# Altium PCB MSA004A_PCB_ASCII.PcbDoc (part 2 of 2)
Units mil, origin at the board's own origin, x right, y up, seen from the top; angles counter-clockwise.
Board outline 2300 x 2720 mil, 2 copper layers (Top Layer, Bottom Layer), stack 62 mil thick; 117 components, 85 nets, 350 pads, 179 vias.
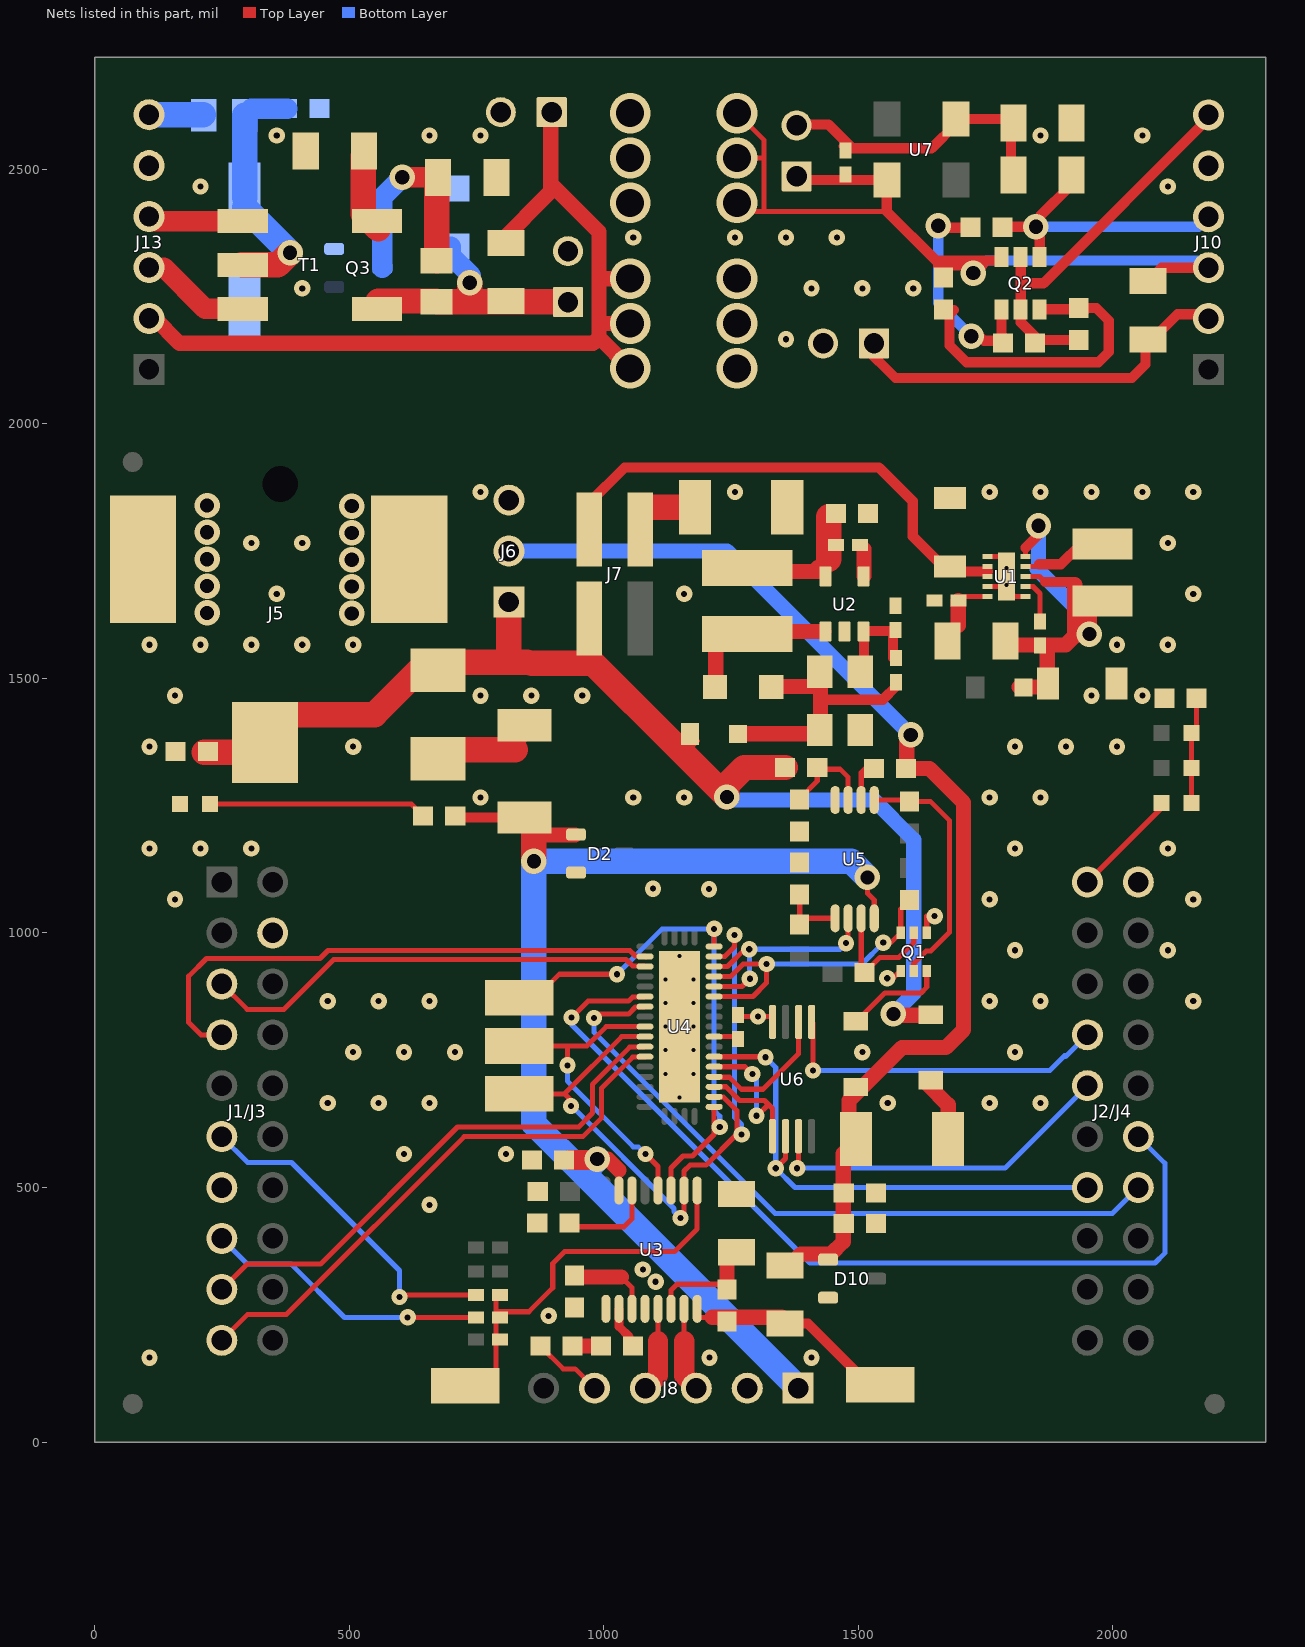
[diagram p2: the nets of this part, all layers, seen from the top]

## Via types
v1: diameter 32, hole 12, Top Layer to Bottom Layer, tented both sides, 125 vias
v2: diameter 50, hole 28, Top Layer to Bottom Layer, 28 vias
v3: diameter 19.68, hole 7.87, Top Layer to Bottom Layer, tented both sides, 14 vias
v4: diameter 80, hole 55, Top Layer to Bottom Layer, 12 vias

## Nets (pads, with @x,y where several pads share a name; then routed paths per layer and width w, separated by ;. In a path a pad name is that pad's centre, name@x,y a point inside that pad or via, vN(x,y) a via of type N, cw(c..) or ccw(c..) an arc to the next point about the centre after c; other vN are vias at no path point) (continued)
GND: C1.2 C2.2 C3.2 C4.2 C5.2 C7.2 C8.2 C9.2 C11.2 C12.2 C14.2 D2.2 D6.2 D10.2 J1/J3.22 J2/J4.20 J5.2 J5.3 J6.3 J8.2 Q1.1 Q1.4 R4.2 R9.2 R10.2 R17.1 R18.2 R23.1 R27.1 U1.1 U1.4 U1.6 U1.11 U2.2 U3.1 U3.4 U4.43 U5.4 U6.4 | length 356.5
  Top Layer w10: U3.4@1081.2,261.86 U3.4@1083.49,264.14 ; R17.1@1248.09,487.09 R17.1@1261,487.09 ; R18.2@1267,835.62 v1@1302.62,835.62 ; v1(1303,836) 1331.61,836 U6.4@1331.61,825.2 ; v1(1557,911) 1568,911 1582.6,925.6 Q1.4@1583.41,925.6 ; Q1.1@1634.59,1000.4 1634.59,1033 v1(1650,1033) ; U1.4@1753.6,1680.32 1782.81,1680.32 U1.11@1782.81,1691.81 ; U1.1@1753.6,1739.37 1791,1739.37 U1.11@1791,1700 v3(1791,1683.62) 1791,1676.69 1807.06,1660.63 U1.6@1828.4,1660.63
  other v1: 108,166 1208,166 1408,166 892,248 1102,315 1077,339 658,466 608,566 808,566 458,666 558,666 658,666 1558,666 1758,666 1858,666 508,766 608,766 708,766 1508,766 1808,766 458,866 558,866 658,866 1758,866 1858,866 2158,866 1808,966 2108,966 158,1066 1758,1066 2158,1066 1207,1086 1097,1087 108,1166 208,1166 308,1166 1808,1166 2108,1166 758,1266 1058,1266 1158,1266 1758,1266 1858,1266 108,1366 508,1366 1808,1366 1908,1366 2008,1366 158,1466 758,1466 858,1466 958,1466 1958,1466 2058,1466 108,1566 208,1566 308,1566 408,1566 508,1566 2008,1566 2108,1566 358,1666 1158,1666 2158,1666 308,1766 408,1766 2108,1766 758,1866 1258,1866 1758,1866 1858,1866 1958,1866 2058,1866 2158,1866
  other v2: 221,1628.5 505,1627.5 505,1680.25 221,1681.25 505,1733 221,1734 505,1785.75 221,1786.75 505,1838.5 221,1839.5
  other v3: 1149,677.22 1121.44,723.48 1176.56,723.48 1121.44,769.74 1176.56,769.74 1121.44,816 1176.56,816 1121.44,862.26 1176.56,862.26 1121.44,908.52 1176.56,908.52 1149,954.78 1791,1716.38
GND_DD: J10.5 J11.2 R35.1
  other v1: 1358,2166 1408,2266 1508,2266 1608,2266 1258,2366 1358,2366 1458,2366 2108,2466 1858,2566 2058,2566
  other v4: 1262,2109 1262,2197 1262,2285
GND_XD: C16.1 C17.2 J12.2 J13.5 J14.2 Q3.2 R38.1 R39.1 R40.1
  other v1: 408,2266 1058,2366 208,2466 358,2566 658,2566 758,2566
  other v4: 1052,2434 1052,2522 1052,2610
GNDP: C13.2 R17.2 U3.6 | length 526.2
  Top Layer w10: U3.6@1132.39,261.86 1132.39,298.39 1144,310 ; C13.2@1242,299.5 C13.2@1242,310 ; R17.2@1242,353.91 R17.2@1261,372.91 ; 1144,310 C13.2@1242,310 ; 1144,310 C13.2@1242,310 ; 1144,310 C13.2@1242,310 ; 1144,310 C13.2@1242,310
  Top Layer w30: C13.2@1242,310 R17.2@1242,353.91
INN: C11.1 U3.3 | length 159.9
  Top Layer w10: 1034.5,324.5 1055.61,303.39 U3.3@1055.61,261.86
  Top Layer w30: C11.1@946,324.5 1034.5,324.5
INP: C10.1 U3.2 | length 81.1
  Top Layer w17: U3.2@1030.02,261.86 1030.02,226.98 1049.99,207.01 C10.1@1049.99,189
INP_DD: J10.2 J11.1 R32.2 | length 777
  Top Layer w20: J11.1@1512,2151 1573,2090 2037,2090 2064,2117 2064,2152 2127,2215 2179.57,2215 J10.2@2187.95,2206.63
INP_XD: J13.2 J14.1 R36.2 | length 1747.7
  Top Layer w30: J13.2@116.5,2208.5 167,2158 979,2158 991,2170 ; R36.2@795.08,2354.93 896,2455.85 896,2610 J14.1@898,2612 ; 896,2472 991,2377 991,2197 ; 993,2285 v4(1052,2285) ; v4(1052,2109) 991,2170 ; v4(1052,2197) 991,2197 ; 991,2170 991,2197
IO: C12.1 C14.1 D10.1 D12.2 J6.2 R15.1 R20.1 R22.2 | length 2320.1
  Top Layer w10: R15.1@1340.25,348.07 1347.32,341 R15.1@1359,341 ; 1413.5,369.65 D10.1@1424.76,358.4
  Top Layer w30: R15.1@1359,341 1387.65,369.65 1446.65,369.65 1470.5,393.5 1470.5,566.5 1493,589 R20.1@1501,589 ; R20.1@1481.95,639.73 1481.95,670.95 1586,775 1672,775 1706.75,809.75 1706.75,1256.25 1640,1323 R22.2@1593.5,1323 ; R22.2@1594.99,1331 1594.99,1380.99 v2(1603,1389)
  Bottom Layer w10: v2(1603,1389) 1603,1376 v2@1608,1371
  Bottom Layer w30: J6.2@810,1761 821,1750 1242,1750 v2@1608,1384
IO_460: C13.1 R15.2 TP4.1 U3.8 | length 437.3
  Top Layer w10: U3.8@1183.57,261.86 1183.57,248.43 1187,245 1217,245 ; R15.2@1356,232.91 R15.2@1366.91,222 ; TP4.1@1521,113 TP4.1@1543,113
  Top Layer w20: R15.2@1356,232.91 1401.09,232.91 TP4.1@1521,113
  Top Layer w30: 1213,245 1217,245 R15.2@1349.91,245
IOREG: C9.1 U3.14 | length 560.1
  Top Layer w10: U3.14@1055.61,494.14 1055.61,438.61 1040,423 ; C9.1@943.5,423 1040,423 ; C9.1@943.5,423 1040,423 ; C9.1@943.5,423 1040,423 ; C9.1@943.5,423 1040,423 ; C9.1@943.5,423 1040,423
MAIN: C1.1 D1.2 D4.1 D11.2 J5.1 J6.1 J7.1 R24.2 | length 2328.8
  Top Layer w10: D4.1@1177.76,1389 1166,1389 1143,1366 1173,1366 D4.1@1184,1377
  Top Layer w30: v2@1571.53,838.47 D11.2@1627,838.47
  Top Layer w50: C1.1@215.5,1355 J5.1@316.06,1355 ; J5.1@344.03,1399.03 374,1429 550,1429 653,1532 849.58,1532 ; 814,1541 J6.1@814,1649 ; 858.57,1529.43 979.57,1529.43 1143,1366 v2(1242,1267) 1242,1291 1276,1325 R24.2@1356.5,1325
  Bottom Layer w30: v2@1234,1270 1242.86,1261.14 1530.86,1261.14 1609,1183 1609,881 v2(1569,841)
MAIN_LOCAL: C2.1 J7.2 U1.2 U1.3 | length 970.8
  Top Layer w10: U1.3@1753.6,1700 1754.6,1709.69
  Top Layer w20: J7.2@972,1792.4 972,1845 1041,1914 1541,1914 1548,1907 1607,1848 1607,1779 1667.9,1718.1 C2.1@1678,1718.1 ; C2.1@1702.24,1709.69 1754.6,1709.69
MEM_CS: J2/J4.37 U6.1 | length 662.2
  Top Layer w10: v1(1411,730) U6.1@1411,822.59
  Bottom Layer w10: v1(1411,730) 1876,730 1905,759 1907,757 J2/J4.37@1950,800
MEM_HOLD: J2/J4.36 U6.7 | length 714.1
  Top Layer w10: v1@1382.8,540.8 U6.7@1382.8,600.8 ; J2/J4.36@1950,683 J2/J4.36@1950,700
  Bottom Layer w10: v1(1380,538) 1788,538 J2/J4.36@1950,700
MEM_MISO: U4.25 U6.2 | length 267.4
  Top Layer w10: U4.25@1216.91,717.57 1217.82,716.67 1246.7,716.67 1270.37,693 1313,693 1382.8,762.8 U6.2@1382.8,825.2
MEM_MOSI: U4.24 U4.26 U6.5 | length 386.2
  Top Layer w10: U4.24@1216.91,697.89 1240.21,697.89 1267,671.1 1315.9,671.1 1323.76,663.24 ; U4.26@1216.91,737.26 1277.74,737.26 v1(1292,723) ; v1(1300,641) 1301.52,641 1323.76,663.24 ; U6.5@1331.61,600.8 1331.61,655.39 1323.76,663.24
  Bottom Layer w10: v1(1292,723) 1300,715 v1(1300,641)
MISO_LP: J1/J3.9 U4.11 | length 1061.6
  Top Layer w10: J1/J3.9@250,300 299.6,349.6 443.66,349.6 713.06,619 951,619 978.25,646.25 978.25,702.68 1051.3,775.72 1080.18,775.72 U4.11@1081.09,776.63
MOSI_LP: J1/J3.10 U4.12 | length 1095.9
  Top Layer w10: J1/J3.10@250,200 301,251 377,251 726,600 959.07,600 996.13,637.06 996.13,695.28 1056.89,756.04 1080.18,756.04 U4.12@1081.09,756.94
NetC3_1: C3.1 D3.2 L1.2 R2.1 R3.2 U1.8 U1.10 | length 881.6
  Top Layer w10: R3.2@1783.09,1576 R3.2@1793.71,1565.38 ; U1.8@1828.4,1700 1856,1700 1867,1689 ; U1.10@1828.4,1739.37 1828.4,1756.4 ; C3.1@1866.07,1483 C3.1@1871,1487.93
  Top Layer w20: 1828.4,1756.4 1854,1782 v2(1854,1800) ; 1867,1689 1925,1689
  Top Layer w30: R3.2@1793.71,1565.38 1871,1565.38 ; D3.2@1816.24,1483 C3.1@1866.07,1483 ; C3.1@1871,1487.93 1871,1565.38 ; 1925,1684 1925,1582.96 1907.42,1565.38 1871,1565.38 ; v2(1954,1587) 1954,1622 1950,1626 L1.2@1976,1652
  Bottom Layer w30: v2(1854,1800) 1854,1718 1851,1715 1950.62,1615.38 v2@1950.62,1599.56
NetC4_1: C4.1 C6.1 D4.2 D5.1 R6.2 | length 536.3
  Top Layer w10: C6.1@1425,1514 C6.1@1426,1513 ; R6.2@1575,1485 R6.2@1575,1493.38
  Top Layer w20: 1424,1458 1548,1458 R6.2@1575,1485
  Top Layer w30: D4.2@1273.24,1391 1417,1391 1426,1400 C6.1@1426,1513 ; D5.1@1330.12,1484 C6.1@1425,1484
NetC5_1: C5.1 L2.1 R5.2 R7.1 U2.5 | length 239.6
  Top Layer w10: R7.1@1450.38,1756 R7.1@1456.5,1762.13
  Top Layer w30: L2.1@1290.96,1710 1427.73,1710 1419.87,1717.87
  Top Layer w50: 1442,1734 C5.1@1442,1817
NetC6_2: C6.2 R6.1 R9.1 U2.3 | length 190.4
  Top Layer w10: C6.2@1505,1514 C6.2@1511.4,1520.4
  Top Layer w20: C6.2@1511.4,1520.4 1511.4,1592.87 1568,1592.87 R6.1@1568,1540.62
NetC10_2: C10.2 R41.2 | length 56
  Top Layer w30: R41.2@938.5,189 C10.2@994.5,189
NetC15_1: C15.1 J12.1 R36.1 R38.2 T1.4 | length 485.6
  Top Layer w10: C15.1@670.87,2241.13 C15.1@672,2240 C15.1@672.09,2239.91
  Top Layer w50: T1.4@556.86,2241.13 C15.1@670.87,2241.13 ; C15.1@672.09,2239.91 776,2239.91 J12.1@915.09,2239.91 ; 737,2239.91 v2(737,2277)
  Bottom Layer w40: R38.2@700,2347.91 700,2330.33 739.5,2290.83 v2@739.5,2274.5
NetC15_2: C15.2 Q3.3 R40.2 | length 406.1
  Top Layer w10: 646.86,2484 R40.2@671.91,2484
  Top Layer w40: v2(604.23,2484.17) 646.69,2484.17 646.86,2484
  Top Layer w50: C15.2@672,2320 R40.2@672,2464
  Bottom Layer w40: Q3.3@565.24,2306 565.24,2445.18 v2(604.23,2484.17)
NetC16_2: C16.2 C17.1 R37.2 T1.2 | length 482.2
  Top Layer w50: T1.2@289.14,2312 360,2312 v2(384,2336)
  Bottom Layer w10: C17.1@295,2425 C17.1@295,2444.3
  Bottom Layer w40: R37.2@308,2619 C16.2@378.5,2619
  Bottom Layer w50: C17.1@295,2425 v2(384,2336) ; C17.1@295,2444.3 R37.2@295,2606
NetD1_1: D1.1 R1.1 | length 189.4
  Top Layer w10: D1.1@675,1341.99 D1.1@693.01,1360 ; 826.45,1360 R1.1@848,1381.55
  Top Layer w50: D1.1@693.01,1360 826.45,1360
NetD5_2: D5.2 L2.2 U2.1 | length 337.3
  Top Layer w10: L2.2@1219.88,1569.88 1238.04,1588.04 1283,1588.04 L2.2@1287.83,1592.87
  Top Layer w30: D5.2@1219.88,1484 L2.2@1219.88,1569.88 ; L2.2@1258,1592 U2.1@1432,1592
NetD6_1: D6.1 R8.2 | length 428.5
  Top Layer w10: D6.1@226.53,1253 622.5,1253 R8.2@645.5,1230
NetD7_2: D7.2 D8.2 D9.2 R10.1 | length 210.1
  Top Layer w10: D7.2@2154.53,1255 D8.2@2154.53,1324 2154.53,1392.94 2164.5,1402.91 R10.1@2164.5,1461
NetD11_1: D11.1 R20.2 | length 133.8
  Top Layer w30: D11.1@1636,712 1636,703 1676.55,662.45 R20.2@1676.55,595
NetD12_1: D12.1 Q1.6 | length 207.1
  Top Layer w10: D12.1@1496,817.47 1504,825.47 1504,834 1552.13,882.13 1623.13,882.13 1634.59,893.59 Q1.6@1634.59,925.6
NetJ9_2: J9.2 R33.1 R34.2 R35.2 U7.3 | length 610.8
  Top Layer w10: J9.2@1373,2573 J9.2@1373,2588 ; R33.1@1466.62,2545 R33.1@1475,2536.62
  Top Layer w20: J9.2@1373,2588 1441,2588 1488,2541 1644,2541 1691.91,2588.91 U7.3@1691.91,2598.66 1795.25,2598.66 1798.91,2595 1799.91,2594 R34.2@1799.91,2488
NetL1_1: L1.1 U1.9 | length 126.6
  Top Layer w10: U1.9@1828.4,1719.69 1850.69,1719.69 1855,1724
  Top Layer w20: 1855,1724 1898,1724 L1.1@1937.04,1763.04
NetQ1_2: Q1.2 R25.1 U5.7 | length 240.5
  Top Layer w10: R25.1@1505.8,928.7 U5.7@1505.8,1028.86 ; R25.1@1512.5,922 1542.62,952.13 1580.13,952.13 1609,981 Q1.2@1609,1000.4
NetQ1_5: Q1.5 R21.1 U5.1 | length 493.8
  Top Layer w10: U5.1@1531.39,1261.14 1598.35,1261.14 R21.1@1601,1258.5 1641.5,1258.5 1678.87,1221.13 1678.87,1000.87 1642.61,964.61 1633.61,964.61 1609,940 Q1.5@1609,925.6
NetQ2_1: Q2.1 R29.1 R31.1 | length 441.7
  Top Layer w20: v2(1657,2389) 1661,2385 R31.1@1712.5,2385 ; v2(1722,2172) 1738,2172 1747,2163 1792.5,2163 1781.6,2173.91 Q2.1@1781.6,2224.82
  Bottom Layer w20: v2(1657,2389) 1657,2237 v2(1722,2172)
NetQ2_3: Q2.3 R28.1 R30.1 | length 642.9
  Top Layer w20: 1688,2223.5 1679.13,2214.63 1679.13,2154.24 1712.49,2120.87 1971.87,2120.87 1992,2141 1992,2203 1967.5,2227.5 R28.1@1933,2227.5 ; Q2.3@1856.4,2224.82 1945.68,2224.82 1946.45,2224.05 R28.1@1933,2224.05
NetR2_2: R2.2 U1.7 | length 88.5
  Top Layer w10: U1.7@1828.4,1680.32 1843.68,1680.32 1844.13,1679.87 1844.13,1679.53 1857,1666.65 R2.2@1857,1612.62
NetR3_1: R3.1 R4.1 U1.5 | length 342.4
  Top Layer w10: R4.1@1696.62,1653 1704.25,1660.63 U1.5@1753.6,1660.63 ; R3.1@1668.91,1576 R3.1@1696.62,1603.71 ; R3.1@1668.91,1576 R3.1@1670.41,1577.5 ; R3.1@1668.91,1576 R3.1@1696.62,1603.71 ; R3.1@1668.91,1576 R3.1@1696.62,1603.71 ; R3.1@1668.91,1576 R3.1@1696.62,1603.71 ; R3.1@1670.41,1577.5 R3.1@1696.62,1603.71 ; R3.1@1670.41,1577.5 R3.1@1696.62,1603.71
  Top Layer w30: R3.1@1696.62,1603.71 R4.1@1696.62,1653
NetR7_2: R7.2 U2.4 | length 67
  Top Layer w10: R7.2@1498.62,1757 1508.62,1757 R7.2@1511.4,1754.22
  Top Layer w30: U2.4@1511.4,1701.13 R7.2@1511.4,1754.22
NetR18_1: R18.1 U4.29 | length 42.1
  Top Layer w10: U4.29@1216.91,796.32 R18.1@1259.06,796.32
NetR22_1: R22.1 U5.2 | length 284.7
  Top Layer w10: U5.2@1505.8,1261.14 1505.8,1315.3 ; R22.1@1523,1332.5 1505.8,1315.3 ; 1505.8,1315.3 R22.1@1522,1331.5 ; 1505.8,1315.3 R22.1@1522,1331.5 ; 1505.8,1315.3 R22.1@1522,1331.5 ; 1505.8,1315.3 R22.1@1522,1331.5 ; 1505.8,1315.3 R22.1@1522,1331.5 ; 1505.8,1315.3 R22.1@1522,1331.5 ; 1505.8,1315.3 R22.1@1522,1331.5 ; 1505.8,1315.3 R22.1@1522,1331.5 ; 1505.8,1315.3 R22.1@1522,1331.5
NetR23_2: R23.2 R24.1 U5.3 | length 244.2
  Top Layer w10: R23.2@1385,1251.5 1385,1263.78 1419.5,1298.28 1419.5,1321.5 1464.5,1321.5 ; R24.1@1416.5,1321.5 1464.5,1321.5 ; U5.3@1480.2,1261.14 1480.2,1305.8 1464.5,1321.5
NetR26_2: R26.2 R27.2 U5.5 | length 136.2
  Top Layer w10: R26.2@1385,1006 R27.2@1385,1072.57 ; R26.2@1385,1028.86 U5.5@1454.61,1028.86
NetR39_2: R39.2 T1.6 | length 155
  Top Layer w50: R39.2@528,2525.91 528,2411.72 T1.6@556.86,2382.87
OUTA: J8.4 U3.5 | length 148.1
  Top Layer w10: 1106.8,198 U3.5@1106.8,243.86
  Top Layer w40: J8.4@1082,106 1106.8,130.8 1106.8,198
OUTA_DD: J9.1 J10.3 Q2.6 R30.2 R32.1 R33.2 U7.1 | length 1795.7
  Top Layer w10: v4(1262,2434) 1279.09,2416.91 1556.09,2416.91 ; v4(1262,2522) 1315.12,2522 ; v4(1262,2610) 1315.12,2556.88 1315.12,2522 ; 1315.12,2419.21 1315.12,2522 ; R30.2@1660.5,2286.5 R30.2@1668.25,2294.25
  Top Layer w20: J9.1@1373,2488 1382.41,2478.59 U7.1@1556.09,2478.59 1556.09,2416.91 1652,2321 1775.42,2321 Q2.6@1781.6,2327.18 ; 1657,2311 v2@1744,2311 ; v2@1721.5,2311 1726,2306.5 v2(1726,2296) ; R32.1@2069,2280.09 2095.54,2306.63 J10.3@2187.95,2306.63
  Bottom Layer w20: v2@1734,2303 1752,2321 2173.57,2321 J10.3@2187.95,2306.63
OUTA_XD: J13.3 T1.3 | length 200.5
  Top Layer w10: J13.3@107.05,2307 J13.3@136,2307
  Top Layer w40: J13.3@136,2307 217,2226 T1.3@274.01,2226
OUTB: J8.3 U3.7 | length 147.8
  Top Layer w10: 1157.98,198 U3.7@1157.98,243.86
  Top Layer w40: 1157.98,198 1157.98,130.02 J8.3@1182,106
OUTB_DD: J10.4 Q2.4 R31.2 R34.1 | length 650.2
  Top Layer w20: R31.2@1775.5,2385 1777.5,2387 v2(1849,2387) 1856.4,2379.6 Q2.4@1856.4,2327.18 1856.4,2407.32 R34.1@1917.09,2468
  Bottom Layer w20: v2(1849,2387) 2168.32,2387 J10.4@2187.95,2406.63
OUTB_XD: J13.4 T1.1 | length 179.8
  Top Layer w10: J13.4@107.05,2407 J13.4@116.05,2398
  Top Layer w40: J13.4@116.05,2398 T1.1@283.14,2398
OWI_RXD: Q1.3 R19.2 U4.33 U4.35 | length 624.9
  Top Layer w10: U4.33@1216.91,875.06 1293.06,875.06 1320,902 v1(1320,939.13) 1274.13,939.13 1249.43,914.43 U4.35@1216.91,914.43 ; v1(1549,981) 1564.01,981 Q1.3@1583.41,1000.4 1583.41,1046.91 R19.2@1601,1064.5
  Bottom Layer w10: v1(1320,939.13) 1507.13,939.13 v1(1549,981)
OWI_TXD: U4.34 U4.36 U5.6 | length 467.6
  Top Layer w10: U4.34@1216.91,894.74 1271.74,894.74 v1(1287,910) v1@1287,904.48 ; U4.36@1216.91,934.11 1243.39,934.11 1277.28,968 v1(1286,968) ; v1(1476,980) 1480.2,984.2 U5.6@1480.2,1028.86
  Bottom Layer w10: v1@1286,911 v1(1286,968) 1464,968 v1(1476,980)
RTRN: J8.5 R41.1 | length 158.4
  Top Layer w10: R41.1@875.5,189 920.5,144 944,144 J8.5@982,106 J8.5@964.5,106
RXD_460: TP1.1 U3.11 U4.22 U4.38 | length 1077.6
  Top Layer w10: TP1.1@834,873 867,873 913,919 v1(1026,919) ; U3.11@1132.39,494.14 1132.39,538.39 1155.83,561.83 1174.67,561.83 1216.91,604.08 U4.22@1216.91,658.52 ; U4.38@1216.91,973.48 v1(1216.91,1008.09)
  Bottom Layer w10: v1(1026,919) 1115.09,1008.09 v1(1216.91,1008.09) 1216.91,651.09 1228,640 v1(1228,619)
RXD_LP: J1/J3.3 U4.3 | length 898
  Top Layer w10: J1/J3.3@250,900 300,850 372,850 469.87,947.87 1044.03,947.87 1056.89,935.02 1080.18,935.02 U4.3@1081.09,934.11
SCLK_460: TP3.1 U3.12 U4.9 | length 625.2
  Top Layer w10: TP3.1@834,778 967,778 1005,816 U4.9@1081.09,816 ; v1(929,740) 929,777 ; v1(1082,566) 1106.8,541.2 U3.12@1106.8,494.14
  Bottom Layer w10: v1(929,740) 929,709 1058,580 1068,580 v1(1082,566)
SCLK_LP: J2/J4.34 U4.27 U6.6 | length 1025.9
  Top Layer w10: U4.27@1216.91,756.94 v1@1318,756.94 ; v1(1338,538) 1357.2,557.2 U6.6@1357.2,600.8
  Bottom Layer w10: v1(1318,756) 1338,736 v1(1338,538) 1376,500 J2/J4.34@1950,500
TCI_CLK: J1/J3.7
TCI_RX: J2/J4.14 U4.7 | length 1375
  Top Layer w10: v1(981,833) 989,841 1049,841 1062.48,854.46 1080.18,854.46 U4.7@1081.09,855.37
  Bottom Layer w10: v1(981,833) 981,805 1337,449 1999,449 J2/J4.14@2050,500
TCI_TX: J2/J4.15 U4.6 | length 1778.4
  Top Layer w10: v1@946.92,843.92 969,866 1048.74,866 1056.89,874.15 1080.18,874.15 U4.6@1081.09,875.06
  Bottom Layer w10: v1(937,834) 937,820 1405,352 2083,352 2102.13,371.13 2102.13,547.87 J2/J4.15@2050,600
TEST: R13.1 R14.1 R16.1 TP5.1 U3.9 | length 785.6
  Top Layer w10: TP5.1@728,111 756,111 788.5,143.5 R14.1@788.5,256 ; R16.1@788.5,289 R14.1@788.5,256 ; U3.9@1183.57,494.14 1183.57,418.57 1139,374 923,374 900,351 900,303 853,256 R14.1@788.5,256
TEST_A: J1/J3.6 R16.2 | length 662
  Top Layer w10: v1(599,285) 600,285 604,289 R16.2@749.38,289
  Bottom Layer w10: J1/J3.6@250,600 301,549 387,549 599,337 v1(599,285)
TEST_D: J1/J3.8 R14.2 | length 563.6
  Top Layer w10: v1(615,245) R14.2@749.38,245
  Bottom Layer w10: J1/J3.8@250,400 300.4,349.6 386.4,349.6 491,245 v1(615,245)
TXD_460: TP2.1 U3.10 U4.10 U4.23 U4.37 | length 1444.2
  Top Layer w10: TP2.1@834,684 923,684 ; 912,684 923,684 ; v1(936,660) 936,671 923,684 ; U4.10@1081.09,796.32 1035.32,796.32 923,684 ; v1(1151,440) 1157.98,446.98 U3.10@1157.98,494.14 1157.98,532.44 1169.49,543.96 1200.96,543.96 1262,605 1262,650.82 1235.52,677.3 1235.15,677.3 1234.24,678.2 U4.23@1216.91,678.2 ; U4.37@1216.91,953.8 1237.8,953.8 1256.13,972.13 1256.13,972.96 1257,973.83 v1(1257,996)
  Bottom Layer w10: v1(936,660) 937.07,660 1138,459.07 1138,453 v1(1151,440) ; v1(1257,996) 1257,638 1271,624 v1(1271,604)
TXD_LP: J1/J3.4 U4.2 | length 1107.2
  Top Layer w10: J1/J3.4@262,788 J1/J3.4@250,800 209.14,800 185,824.14 185,915 220,950 443,950 458.7,965.7 462.42,965.7 462.47,965.75 1051.43,965.75 1062.48,954.7 1081.39,954.7 U4.2@1083.09,953
V_DIAG_LED: D7.1 J2/J4.40 | length 215.3
  Top Layer w10: J2/J4.40@1950,1100 2095.47,1245.47 D7.1@2095.47,1255
VIN_USB_ONLY: J7.4 R5.1 | length 141.7
  Top Layer w10: J7.4@1072,1792.4 1072,1820 J7.4@1088,1836
  Top Layer w50: J7.4@1088,1836 R5.1@1179.45,1836
VPWR: C8.1 D2.1 J8.1 R1.2 R8.1 U3.15 U5.8 | length 2424.5
  Top Layer w10: R1.2@863,1208.47 879.06,1192.4 ; v2@985.5,554 v2(987.5,556) ; U3.15@1030.02,494.14 1030.02,533.98 ; v2(1518,1109) 1518,1078 1531.39,1064.61 U5.8@1531.39,1028.86
  Top Layer w20: R8.1@708.5,1227 R1.2@800,1227
  Top Layer w30: 879.06,1192.4 D2.1@943.76,1192.4 ; v2(987.5,556) 1008,556 1030.02,533.98
  Top Layer w40: C8.1@933.5,554 v2@985.5,554
  Top Layer w50: v2(863,1141) R1.2@863,1208.47
  Bottom Layer w50: v2(987.5,556) 959.75,528.25 ; J8.1@1382,106 959.75,528.25 ; v2@1510,1117 1486,1141 v2(863,1141) 863,625 959.75,528.25
VPWR_DD: J10.6 Q2.2 Q2.5 R28.2 R29.2 | length 767.2
  Top Layer w20: Q2.5@1819,2327.18 1819,2276 ; R28.2@1933,2164.51 1857,2164.51 1855.5,2163 1819,2199.5 Q2.2@1819,2224.82 1819,2276 ; J10.6@2187.95,2606.63 2187.95,2599.98 1863.97,2276 1819,2276
VPWR_XD: J13.6 R37.1 | length 106.9
  Bottom Layer w50: J13.6@107.05,2607 R37.1@214,2607
pads on no net: D2.3 D10.3 FID1.1 FID2.1 FID3.1 FID4.1 FID5.1 FID6.1 J1/J3.23 J1/J3.24 J1/J3.25 J1/J3.26 J1/J3.27 J1/J3.28 J1/J3.29 J1/J3.30 J2/J4.11 J2/J4.12 J2/J4.13 J2/J4.16 J2/J4.19 J2/J4.31 J2/J4.32 J2/J4.33 J2/J4.35 J5.0 SH-J1.0 U4.1 U4.4 U4.8 U4.14 U4.15 U4.16 U4.17 U4.18 U4.19 U4.20 U4.21 U4.28 U4.30 U4.31 U4.32 U4.40 U4.41 U4.42 U6.3 U7.2 U7.4

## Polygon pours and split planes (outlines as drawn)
GND_DD on Top Layer "Top-GNDD" (solid, pour order 19): 1159,2720 1159,2012 2300,2012 2300,2720
GND_XD on Top Layer "Top-GNDX" (solid, pour order 17): 0,2009 1141,2009 1141,2720 0,2720
GND on Top Layer "Top-GND" (solid, pour order 15): 0,0 1224,0 1224,152 1226.64,158.36 1236.64,168.36 cw(c1243,162) 1243,171 1304.99,171 1311.36,168.36 1340.36,139.36 1343,133 1343,0 2300,0 2300,1991 0,1991
GND_DD on Bottom Layer "Btm-GNDD" (solid, pour order 18): 1159,2800 1159,2012 2300,2012 2300,2800
GND_XD on Bottom Layer "Btm-GNDX" (solid, pour order 16): 0,2009 1141,2009 1141,2800 0,2800
GND on Bottom Layer "Btm-GND" (solid, pour order 14): 0,0 1161.57,0 1161.57,26.45 750,450.6 750,500 842.76,500 842.76,494.76 1224,113.52 1224,9 1341.8,9 1341.8,101 1360,119.2 1360,3 1359.49,0 2300,0 2300,1991 0,1991

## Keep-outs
Keep-Out Layer:
  text ".Layer_Name" at 577,-858.49 h60

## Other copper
Top Layer:
  rectangle net NetR39_2: 497,2354 605.32,2422
  rectangle net NetC15_1: 497,2201 605.32,2269
  rectangle net OUTB_XD: 239,2355 347.32,2423
  rectangle net NetC16_2: 239,2278 347.32,2346
  rectangle net OUTA_XD: 239,2201 347.32,2269
  rectangle net NetC5_1: 1326,1713 1445,1838
  rectangle net INP_XD: 979,2109 1052,2300
  rectangle net OUTA_DD: 1261,2419.21 1315.12,2640
  text ".Layer_Name" at 577,-858.49 h60
Bottom Layer:
  text ".Layer_Name" at 577,-858.49 h60

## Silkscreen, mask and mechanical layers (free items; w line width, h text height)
Top Overlay:
  lines w10: 947,1527 947,1320 1099,1320 1099,1527 ; 1002,2088 1002,2313 ; 1002,2409 1002,2634 ; 1022,1321 1022,1528 ; 1313,2088 1313,2313 ; 1313,2409 1313,2634
  text "-" at 1093,2619 h72.83
  text "+" at 1188.87,2600.23 h72.83
  text "VPWR" at 183.13,2591 h30 r45
  text "-" at 1093,2530.5 h72.83
  text "+" at 1188.87,2511.73 h72.83
  text "+" at 900,2508 h72.83
  text "GND" at 183.38,2491.61 h30 r45
  text "-" at 1093,2442 h72.83
  text "+" at 1188,2435 h72.83
  text "OUTB" at 183.38,2391.96 h30 r45
  text "+" at 1356,2389 h72.83
  text "OUTA" at 183.38,2292.31 h30 r45
  text "-" at 1205,2242 h72.83
  text "+" at 1093,2235 h72.83
  text "+" at 1502,2219 h72.83
  text "RTRN" at 183.13,2192.41 h30 r45
  text "-" at 1205,2153.5 h72.83
  text "+" at 1093,2146.5 h72.83
  text "+" at 900,2139 h72.83
  text "DCPL" at 183.38,2093 h30 r45
  text "-" at 1205,2065 h72.83
  text "+" at 1093,2058 h72.83
  text "Transformer Driven" at 310,2047 h72.83
  text "Direct Driven" at 1526,2047 h72.83
  text "GND" at 753,1817 h60 r90
  text "IO" at 753,1729 h60 r90
  text "PWR" at 754,1578 h60 r90
  text "DS-LED" at 1868.03,1375.97 h60
  text "X-EXT" at 1004,1341 h60 r90
  text "LP-USB" at 1082,1340 h60 r90
  text "FD-LED" at 1871,1305 h60
  text "Alt Pwr" at 932,1272 h60
  text "VD-LED" at 1864,1237 h60
  text "VPWR-LED" at 264,1234 h60
  text "Modes" at 947,1230 h60
  text "1" at 239,1167 h55
  text "21" at 323,1167 h55
  text "40" at 1925,1167 h55
  text "20" at 2024,1167 h55
  text "J1" at 133,1164 h72.83
  text "J3" at 405,1164 h72.83
  text "J4" at 1825,1164 h72.83
  text "J2" at 2104,1164 h72.83
  text "5V" at 480.5,1078 h72.83
  text "3V3" at 23.75,1076.5 h72.83
  text "GND" at 2146.25,1075.75 h72.83
  text "GND" at 449.25,977 h72.83
  text "VDLED" at 1790,968 h60 r45
  text "COM_P" at 2100,899 h60 r315
  text "DECA*" at 97,891 h60 r45
  text "FDLED" at 1796,868 h60 r45
  text "COM_S" at 2100,798 h60 r315
  text "UARX" at 110.66,796 h60 r45
  text "DSLED" at 1793,768 h60 r45
  text "MCS" at 1836,706 h60 r45
  text "UATX" at 114.86,697 h60 r45
  text "TCITX" at 2090.86,600 h60 r315
  text "MHLD" at 1814,580 h60 r45
  text "DECD*" at 96.76,579 h60 r45
  text "TCIRX" at 2090.86,500 h60 r315
  text "TSTA*" at 108,490 h60 r45
  text "BOOSTXL-PGA460" at 682,442 h85 r90
  text "MSA004A" at 741,441 h70 r90
  text "SCLK" at 1806,389 h60 r45
  text "TCICK" at 96,374 h60 r45
  text "TSTD*" at 103.2,291 h60 r45
  text "MISO" at 123,201 h60 r45
  text "31" at 1928,98 h55
  text "11" at 2027,98 h55
  text "10" at 227,97 h55
  text "30" at 325,97 h55
  text "MOSI" at 122,96 h60 r45
  text "GND" at 1339,74.62 h30 r90
  text "DCPL" at 941,71 h30 r90
  text "RTRN" at 1041,67 h30 r90
  text "OUTA" at 1141,66 h30 r90
  text "OUTB" at 1240,66.38 h30 r90
  text "VPWR" at 1442,64 h30 r90
  text ".Layer_Name" at 577,-858.49 h60
Bottom Overlay:
  drawing of 3493 lines, arcs and shapes, not listed
  text "MSA004A" at 1230,2660 h40
  text "-" at 1093,2619 h72.83
  text "VPWR" at 2126.13,2606 h30 r45
  text "+" at 1188.87,2600.23 h72.83
  text "-" at 1093,2530.5 h72.83
  text "+" at 1188.87,2511.73 h72.83
  text "+" at 900,2508 h72.83
  text "GND" at 2125.87,2506.61 h30 r45
  text "-" at 1093,2442 h72.83
  text "+" at 1188,2435 h72.83
  text "OUTB" at 2125.87,2406.96 h30 r45
  text "+" at 1356,2389 h72.83
  text "OUTA" at 2125.87,2307.31 h30 r45
  text "-" at 1205,2242 h72.83
  text "+" at 1093,2235 h72.83
  text "+" at 1502,2219 h72.83
  text "RTRN" at 2126.13,2207.41 h30 r45
  text "-" at 1205,2153.5 h72.83
  text "+" at 1093,2146.5 h72.83
  text "+" at 900,2139 h72.83
  text "DCPL" at 2125.89,2108 h30 r45
  text "-" at 1205,2065 h72.83
  text "+" at 1093,2058 h72.83
  text "BOOSTXL-PGA460 Daughtercard" at 1432,2034 h40
  text "1" at 297,1160 h55
  text "21" at 397.5,1160 h55
  text "40" at 1999,1160 h55
  text "20" at 2097.5,1160 h55
  text "J4" at 1902.5,1158 h72.83
  text "J1" at 202.5,1154 h72.83
  text "J3" at 479,1154 h72.83
  text "J2" at 2179,1153.5 h72.83
  text "GND" at 2287,1077.5 h72.83
  text "5V" at 553,1077 h72.83
  text "3V3" at 133.25,1076 h72.83
  text "GP40" at 1902,1046 h72.83
  text "GND" at 588,977.5 h72.83
  text "AIN2*" at 197.5,952 h72.83
  text "GP39" at 1902.5,945 h72.83
  text "GP38" at 1902.5,851 h72.83
  text "GP18" at 2284,847 h72.83
  text "UARX" at 207.01,843 h72.83
  text "UATX" at 207.01,753 h72.83
  text "GP17" at 2284,752 h72.83
  text "GP37" at 1902.5,745 h72.83
  text "GP36" at 1902.5,652 h72.83
  text "GP5*" at 197.5,643 h72.83
  text "PGA460-Q1 BoosterPack" at 1717,572.32 h72.83
  text "AIN6*" at 197.5,554 h72.83
  text "MOSI" at 2279,553 h72.83
  text "BOOSTXL-PGA460" at 1717,460.22 h72.83
  text "SCLK" at 1902.5,452 h72.83
  text "MISO" at 2280,447 h72.83
  text "CLK" at 197.5,444 h72.83
  text "Rev A" at 1717,392.36 h60
  text "GP8*" at 197.5,353 h72.83
  text "SOMI" at 197.5,246 h72.83
  text "SIMO" at 197.5,153 h72.83
  text "31" at 1999,92 h55
  text "11" at 2097.5,92 h55
  text "10" at 300,89 h55
  text "30" at 400,89 h55
  text ".Layer_Name" at 577,-858.49 h60
Top Paste:
  text ".Layer_Name" at 577,-858.49 h60
Bottom Paste:
  text ".Layer_Name" at 577,-858.49 h60
Top Solder:
  rectangle: 496.97,2354 605.29,2422
  rectangle: 496.97,2201 605.29,2269
  rectangle: 238.97,2355 347.29,2423
  rectangle: 238.97,2278 347.29,2346
  text ".Layer_Name" at 577,-858.49 h60
  text ".Layer_Name" at 577,-858.49 h60
Bottom Solder:
  text ".Layer_Name" at 577,-858.49 h60
Drill Guide:
  text ".Layer_Name" at 577,-858.49 h60
M1 Board Outline:
  lines w10: 0,2000 2300,2000 ; 0,0 2300,0 2300,2720 0,2720 0,0
  text ".Layer_Name" at 577,-858.49 h60
M2 Board Dimensions:
  rectangle: 125,-400 500,-275
  rectangle: 0,-275 125,-150
  lines w7: 0,-275 1000,-275 ; 125,-400 125,-150 ; 250,-400 250,-150 ; 500,-400 500,-150 ; 750,-400 750,-150 ; 0,-400 0,-150 1000,-150 1000,-400 0,-400
  text ".Layer_Name" at 577,-858.49 h60
M3 3D STEP Top:
  text ".Layer_Name" at 577,-858.49 h60
M4 3D STEP Bottom:
  text ".Layer_Name" at 577,-858.49 h60
M5 Assembly Top:
  lines w10: -292,-930.17 6308,-930.17 ; -292,-726.83 6310,-726.83 ; -292,-523.5 -292,-1133.5 3713,-1133.5 6310,-1133.5 6310,-523.5 -291.5,-523.5 -291.5,-1133.5 1284,-1133.5 ; 2173,-1133.5 2173,-523.5 ; 3440,-726.83 3440,-523.5 ; 4280,-726.83 4280,-523.5 ; 4902,-1140 4902,-937.17
  text "COMPONENTS MARKED 'DNP' SHOULD NOT BE POPULATED." at 1153.5,-318.5 h60
  text "ASSEMBLY VARIANT:" at 1153,-434 h60
  text ".VariantName" at 2189,-434 h60
  text "PCB VIEWED FROM TOP SIDE" at -228.5,-655.67 h60
  text "BOARD #:" at 2248,-655.67 h60
  text ".PRJ_Number" at 2793.5,-655.67 h60
  text "REV:" at 3638,-655.67 h60
  text ".PCB_Rev" at 3929.5,-655.67 h60
  text "SVN REV:" at 4476,-655.67 h60
  text ".VersionControl_RevNumber" at 4982,-655.67 h60
  text "TID #:" at 2248,-859 h60
  text ".TID" at 2793.5,-859 h60
  text "PLOT NAME =" at -228.5,-1064.34 h60
  text ".plot_File_Name" at 577,-1064.34 h60
  text "GENERATED    :" at 2250,-1064.34 h60
  text ".Print_Date" at 3119.5,-1064.34 h60
  text ".Print_Time" at 3848.5,-1064.34 h60
  text "TEXAS INSTRUMENTS" at 5113,-1064.34 h60
M6 Assembly Bottom:
  lines w10: -292.5,-727.33 6309.5,-727.33 ; -290.5,-930.67 6309.5,-930.67 ; 1115.5,-1140.5 1115.5,-937.67 ; 1737.5,-727.33 1737.5,-524 ; 2577.5,-727.33 2577.5,-524 ; 3844.5,-1134 3844.5,-524 ; 4733.5,-1134 6309,-1134 6309,-524 -292.5,-524 -292.5,-1134 2304.5,-1134 6309.5,-1134 6309.5,-524
  text "COMPONENTS MARKED 'DNP' SHOULD NOT BE POPULATED." at 6102,-318 h60
  text ".VariantName" at 5058,-434 h60
  text "ASSEMBLY VARIANT:" at 6097,-434 h60
  text ".VersionControl_RevNumber" at 1035.5,-656.17 h60
  text "SVN REV:" at 1541.5,-656.17 h60
  text ".PCB_Rev" at 2088,-656.17 h60
  text "REV:" at 2379.5,-656.17 h60
  text ".PRJ_Number" at 3224,-656.17 h60
  text "BOARD #:" at 3769.5,-656.17 h60
  text "PCB VIEWED FROM BOTTOM SIDE" at 6246,-656.17 h60
  text ".TID" at 3224,-859.5 h60
  text "TID #:" at 3769.5,-859.5 h60
  text "TEXAS INSTRUMENTS" at 904.5,-1064.84 h60
  text ".Print_Time" at 2169,-1064.84 h60
  text ".Print_Date" at 2898,-1064.84 h60
  text "GENERATED    :" at 3767.5,-1064.84 h60
  text ".plot_File_Name" at 5440.5,-1064.84 h60
  text "PLOT NAME =" at 6246,-1064.84 h60
M9 Title Sheet:
  lines w10: -491.5,1041.5 -291.5,1041.5 ; -491.5,3416.5 -291.5,3416.5 ; -491.5,5791.5 -291.5,5791.5 ; 2008.5,-1333.5 2008.5,-1133.5 ; 2008.5,7966.5 2008.5,8166.5 ; 4508.5,-1333.5 4508.5,-1133.5 ; 4508.5,7966.5 4508.5,8166.5 ; 6321,-1133.5 6321,-523.5 11303.5,-523.5 ; 7008.5,-1333.5 7008.5,-1133.5 ; 7008.5,7966.5 7008.5,8166.5 ; 9508.5,-1333.5 9508.5,-1133.5 ; 9508.5,7966.5 9508.5,8166.5 ; 11303.5,-1133.5 11303.5,-523.5 ; 11303.5,-823.5 14303.5,-823.5 ; 11303.5,-223.5 14303.5,-223.5 ; 11304.5,370.5 14304.5,370.5 ; 12008.5,-1333.5 12008.5,-1133.5 ; 12008.5,7966.5 12008.5,8166.5 ; 12808.5,-1123.5 12808.5,-523.5 ; 14303.5,-523.5 11303.5,-523.5 ; 14303.5,76.5 11303.5,76.5 ; 14308.5,66.5 14308.5,-1133.5 ; 14308.5,871 11304.5,871 11303.5,871 11303.5,370.5 11303.5,76.5 ; 14308.5,1041.5 14508.5,1041.5 ; 14308.5,3416.5 14508.5,3416.5 ; 14308.5,5791.5 14508.5,5791.5 ; 11303.5,-523.5 11303.5,76.5 ; 14308.5,-1133.5 -291.5,-1133.5 -291.5,7966.5 14308.5,7966.5 14308.5,-1133.5 ; -491.5,-1333.5 14508.5,-1333.5 14508.5,8166.5 -491.5,8166.5 -491.5,-1333.5
  text "1" at 739.84,8036.5 h70
  text "2" at 3235.5,8036.5 h70
  text "3" at 5724.84,8036.5 h70
  text "4" at 8231.51,8036.5 h70
  text "5" at 10730.5,8036.5 h70
  text "6" at 13235.5,8036.5 h70
  text "A" at -416.5,6893.5 h70
  text "A" at 14383.5,6893.5 h70
  text "B" at -416.5,4513.5 h70
  text "B" at 14383.5,4513.5 h70
  text "C" at -416.5,2138.5 h70
  text "C" at 14383.5,2138.5 h70
  text "PROJECT TITLE:" at 11343.5,277.5 h45
  text ".PRJ_Title" at 11393.5,144.17 h70
  text "DESIGNED FOR:" at 11343.5,-23.5 h45
  text ".PRJ_Customer" at 11393.5,-163.5 h70
  text "D" at -416.5,-231.5 h70
  text "D" at 14383.5,-231.5 h70
  text "FILE NAME:" at 11343.5,-323.5 h45
  text ".PCB_File_Name_No_Path" at 11393.5,-443.5 h70
  text "Texas Instruments (TI) and/or its licensors do not warrant the accuracy or completeness of this specification" at 6374,-605.34 h45
  text "ENGINEER:" at 11343.5,-613.5 h45
  text "LAYOUT BY:" at 12848.5,-613.5 h45
  text "or any information contained therein. TI and/or its licensors do not warrant that this design will meet" at 6329.01,-718 h45
  text ".PRJ_Engineer" at 11393.5,-768.49 h70
  text ".PCB_Layout" at 12899,-768.49 h70
  text "the specifications, will be suitable for your application or fit for any particular purpose, or will operate in" at 6329.01,-830.67 h45
  text ".Layer_Name" at 577,-858.49 h60
  text "ALTIUM DESIGNER VERSION:" at 12848.5,-923.5 h45
  text "an implementation. TI and/or its licensors do not warrant that the design is production worthy. You should" at 6329.01,-943.33 h45
  text "completely validate and test your design implementation to confirm the system functionality for your application." at 6374,-1056 h45
  text ".print_Scale" at 11393.5,-1056.83 h70
  text ".Application_BuildNumber" at 12899,-1056.83 h70
  text "1" at 739.84,-1263.5 h70
  text "2" at 3235.5,-1263.5 h70
  text "3" at 5724.84,-1263.5 h70
  text "4" at 8231.51,-1263.5 h70
  text "5" at 10730.5,-1263.5 h70
  text "6" at 13235.5,-1263.5 h70
M10 Fab Notes:
  drawing of 177 lines, arcs and shapes, not listed
  text "DESIGN INFORMATION" at 12378.02,6201 h60
  text "MIN. TRACK WIDTH:" at 11733.46,6021 h60
  text "8" at 12829.7,6021 h60
  text "MIL" at 12984.46,6021 h60
  text "MIN. CLEARANCE:" at 11733.46,5889 h60
  text "0.2" at 12769.7,5889 h60
  text "mm" at 12984.46,5889 h60
  text "MIN. VIA PAD SIZE:" at 11733.46,5757 h60
  text "24" at 12799.71,5757 h60
  text "MIL" at 12984.46,5757 h60
  text "0.05mm (2MIL)" at 12428.46,5615.29 h60
  text "MINIMUM ANNULAR RING" at 11404.23,5611 h60
  text "EXTERNAL" at 13136.46,5611 h60
  text "PER" at 11604.23,5493 h60
  text "IPC-D-275 CLASS 2 LEVEL C" at 11824.23,5493 h60
  text "MIL, HOLES" at 13312.46,5380.71 h60
  text "+/-" at 12920,5380 h60
  text "+/-" at 13774,5380 h60
  text "REGISTRATION TOLERANCES:" at 11404.23,5375 h60
  text "METAL" at 12604,5375 h60
  text "5" at 13180.2,5375 h60
  text "3" at 14013.2,5375 h60
  text "MIL" at 14129.46,5375 h60
  text "+/-" at 13774,5262 h60
  text "HOLE SIZE TOLERANCE (UNLESS OTHERWISE SPECIFIED):" at 11404.23,5257 h60
  text "3" at 14013.2,5257 h60
  text "MIL" at 14129.46,5257 h60
  text "MATERIAL:" at 11329.46,5047.54 h60
  text "FR-4 High Tg" at 12315.9,4907.21 h60
  text "FR-408" at 11750.46,4898.64 h60
  text "OTHER" at 13238.46,4898.64 h60
  text "X" at 12161,4895 h60
  text "62 MIL (1.6mm) +/-10%" at 12070.56,4735.92 h60
  text "THICKNESS:" at 11404.23,4731.64 h60
  text "X" at 11942.4,4731.64 h60
  text "OTHER" at 13355.46,4731.64 h60
  text "TOLERANCE:" at 11404.23,4573.64 h60
  text "X" at 12243.53,4573.64 h60
  text "ANSI IPC-6012 TYPE 3 CLASS 2" at 12430.48,4573.64 h60
  text "OTHER +/-" at 12430.46,4417.64 h60
  text "BOW & TWIST:" at 11404.23,4260.64 h60
  text "X" at 12243.53,4260.64 h60
  text "ANSI IPC-6012 TYPE 3 CLASS 2" at 12430.48,4260.64 h60
  text "OTHER +/-" at 12430.46,4102.13 h60
  text "DRILLING:" at 11329.46,3963.64 h60
  text "REFERENCE:" at 11404.23,3846.64 h60
  text "X" at 12052.46,3846.64 h60
  text "AS SHOWN" at 12239.46,3846.64 h60
  text "X" at 12953.46,3846.64 h60
  text "NC_DRILL FILES" at 13090.46,3846.64 h60
  text "PTH COPPER THICKNESS:" at 11404.23,3688.64 h60
  text "X" at 12534.46,3688.64 h60
  text "20-30 um" at 12671.46,3688.64 h60
  text "OTHER" at 13388.46,3688.64 h60
  text "BOARD FINISH:" at 11329.46,3529.64 h60
  text "SILKSCREEN:" at 11484.68,3411.64 h60
  text "X" at 12433.46,3411.64 h60
  text "TOP" at 12559.46,3411.64 h60
  text "X" at 12943.46,3411.64 h60
  text "BOTTOM" at 13070.46,3411.64 h60
  text "SILKSCREEN COLOR:" at 11484.68,3244.64 h60
  text "X" at 12432.42,3244.64 h60
  text "WHITE" at 12559.46,3244.64 h60
  text "OTHER" at 13070.46,3244.64 h60
  text "RED" at 13677.46,3094.44 h60
  text "GREEN" at 12690.46,3085.44 h60
  text "OTHER" at 13308.46,3085.44 h60
  text "X" at 13158,3084 h60
  text "SOLDER RESIST COLOR:" at 11484.68,3074.64 h60
  text "X" at 12563.42,2915.44 h60
  text "MATTE" at 12690.46,2915.44 h60
  text "SEMI-GLOSS" at 13308,2914.8 h60
  text "IMMERSION GOLD (ENIG)" at 12390.46,2726.92 h60
  text "ENEPIG" at 13728,2723.64 h60
  text "SURFACE FINISH:" at 11329.46,2722.64 h60
  text "X" at 12203.51,2722.64 h60
  text "IMM. TIN/SILVER OR EQUIV" at 11659,2565.64 h60
  text "OTHER" at 13090.46,2565.64 h60
  text "ARRAY/PANEL:" at 11329.46,2386.64 h60
  text "CUT AND TRIM PER M1 BOARD OUTLINE" at 12390.46,2382.35 h60
  text "N.C. ROUTE" at 12390.46,2230.64 h60
  text "X" at 13069.46,2230.64 h60
  text "V. SCORE" at 13256.46,2230.64 h60
  text "CERTIFICATION:" at 11329.46,2093.64 h60
  text "MATERIALS AND WORKMANSHIP FOR ALL PCBS" at 12054.46,2093.64 h60
  text "TO MEET OR EXCEED THE REQUIREMENTS OF:" at 12054.46,1995.64 h60
  text "Score line to separate motherboard from daughtercard post-assembly. Seperate daughtercard post-assembly for individual packaging of motherboard and daughtercard." at 2375,1981 h72.83
  text "X" at 11680.96,1859.13 h60
  text "ANSI IPC-A-600F CLASS ->" at 11819.96,1859.13 h60
  text "X" at 13459.02,1859.13 h60
  text "2" at 13577.96,1859.14 h60
  text "1" at 13262.96,1857.64 h60
  text "3" at 13931.96,1857.64 h60
  text "X" at 12495.02,1699.64 h60
  text "RoHS" at 12631.96,1699.64 h60
  text "OTHER" at 13276.36,1699.64 h60
  text "PER ORDER" at 13673.42,1699.64 h60
  text "ALL BOARDS MUST MEET OR EXCEED UL94-V0 REQUIREMENTS." at 11357,1534 h60
  text "PCB MUST BEAR THE UL94V-0 UL REGISTERED MATERIAL ID NUMBER" at 11357,1414 h60
  text "ADDITIONAL REQUIREMENTS:" at 11329.46,1240.64 h60
  text "MICROSECTION:" at 11404.23,1125.64 h60
  text "YES" at 12309.96,1125.64 h60
  text "REQUIRED" at 13171.46,969.49 h60
  text "BARE BOARD ELEC. TEST:" at 11404.23,966.64 h60
  text "NONE" at 12709.96,966.64 h60
  text "X" at 13044.46,966.64 h60
  text "PER ORDER" at 13763.46,966.64 h60
  text ".Layer_Name" at 577,-858.49 h60
M11 Gerber Information:
  lines w10: -292,-930.17 6308,-930.17 ; -292,-726.83 6310,-726.83 ; -292,-523.5 -292,-1133.5 3713,-1133.5 6310,-1133.5 6310,-523.5 -291.5,-523.5 -291.5,-1133.5 1284,-1133.5 ; 2173,-1133.5 2173,-523.5 ; 3440,-726.83 3440,-523.5 ; 4280,-726.83 4280,-523.5 ; 4902,-1140 4902,-937.17
  text "ALL ARTWORK VIEWED FROM TOP SIDE" at -228.5,-655.67 h60
  text "BOARD #:" at 2248,-655.67 h60
  text ".PRJ_Number" at 2793.5,-655.67 h60
  text "REV:" at 3638,-655.67 h60
  text ".PCB_Rev" at 3929.5,-655.67 h60
  text "SVN REV:" at 4476,-655.67 h60
  text ".VersionControl_RevNumber" at 4982,-655.67 h60
  text "LAYER NAME =" at -228.5,-858.49 h60
  text "TID #:" at 2248,-859 h60
  text ".TID" at 2793.5,-859 h60
  text "PLOT NAME =" at -228.5,-1064.34 h60
  text ".plot_File_Name" at 577,-1064.34 h60
  text "GENERATED    :" at 2250,-1064.34 h60
  text ".Print_Date" at 3119.5,-1064.34 h60
  text ".Print_Time" at 3848.5,-1064.34 h60
  text "TEXAS INSTRUMENTS" at 5113,-1064.34 h60
M12 Stackup:
  drawing of 191 lines, arcs and shapes, not listed
  text "Layer" at 9790.34,7830 h60
  text "Name" at 10200.26,7830 h60
  text "Material" at 11130,7830 h60
  text "Thickness" at 11989.77,7830 h60
  text "Constant" at 12639.6,7830 h60
  text "Board Layer Stack" at 13209.46,7830 h60
  text "1" at 9790.34,7710 h60
  text "Top Overlay" at 10200.26,7710 h60
  text "2" at 9790.34,7590 h60
  text "Top Solder" at 10200.26,7590 h60
  text "Solder Resist" at 11130,7590 h60
  text "0.40mil" at 11989.77,7590 h60
  text "3.5" at 12639.6,7590 h60
  text "3" at 9790.34,7470 h60
  text "Top Layer" at 10200.26,7470 h60
  text "Copper" at 11130,7470 h60
  text "1.40mil" at 11989.77,7470 h60
  text "4" at 9790.34,7350 h60
  text "Dielectric1" at 10200.26,7350 h60
  text "FR-4" at 11130,7350 h60
  text "59.20mil" at 11989.77,7350 h60
  text "4.8" at 12639.6,7350 h60
  text "5" at 9790.34,7230 h60
  text "Bottom Layer" at 10200.26,7230 h60
  text "Copper" at 11130,7230 h60
  text "1.40mil" at 11989.77,7230 h60
  text "6" at 9790.34,7110 h60
  text "Bottom Solder" at 10200.26,7110 h60
  text "Solder Resist" at 11130,7110 h60
  text "0.40mil" at 11989.77,7110 h60
  text "3.5" at 12639.6,7110 h60
  text "7" at 9790.34,6990 h60
  text "Bottom Overlay" at 10200.26,6990 h60
  text ".Layer_Name" at 577,-858.49 h60
M13 Component Bodies Top:
  text ".Layer_Name" at 577,-858.49 h60
M14 Component Bodies Bottom:
  text ".Layer_Name" at 577,-858.49 h60
M15 Courtyards Top:
  text ".Layer_Name" at 577,-858.49 h60
M16 Courtyards Bottom:
  text ".Layer_Name" at 577,-858.49 h60
Drill Drawing:
  circle w10: c2833.72,2693.32 r27.63
  lines w10: 2806.09,2320.36 2833.72,2292.74 2861.34,2320.36 2833.72,2347.99 2806.09,2320.36 ; 2806.09,2417.06 2861.34,2417.06 2861.34,2472.31 2806.09,2472.31 2806.09,2417.06 ; 2806.09,2596.63 2861.34,2596.63 2833.72,2541.38 2806.09,2596.63 ; 2806.09,2790.02 2833.72,2803.83 2861.34,2790.02 2847.53,2817.64 2861.34,2845.27 2833.72,2831.46 2806.09,2845.27 2819.9,2817.64 2806.09,2790.02 ; 2806.09,2928.15 2819.9,2928.15 2833.72,2914.34 2847.53,2928.15 2861.34,2928.15 2847.53,2941.96 2861.34,2955.78 2847.53,2955.78 2833.72,2969.59 2819.9,2955.78 2806.09,2955.78 2819.9,2941.96 2806.09,2928.15 ; 2806.09,3038.66 2806.09,3052.47 2819.9,3066.28 2806.09,3080.1 2806.09,3093.91 2819.9,3093.91 2833.72,3080.1 2847.53,3093.91 2861.34,3093.91 2861.34,3080.1 2847.53,3066.28 2861.34,3052.47 2861.34,3038.66 2847.53,3038.66 2833.72,3052.47 2819.9,3038.66 2806.09,3038.66
  lines w12: 2756,2255.44 5987.49,2255.44 ; 2756,3125.68 5987.49,3125.68 ; 3093.86,2131.12 3093.86,3250 ; 3425.86,2131.12 3425.86,3250 ; 4062.43,2131.12 4062.43,3250 ; 4321.57,2131.12 4321.57,3250 ; 4696.72,2131.12 4696.72,3250 ; 5421.05,2131.12 5421.05,3250 ; 2756,2131.12 5987.49,2131.12 5987.49,3250 2756,3250 2756,2131.12
  text "Symbol" at 2830.59,3162.98 h72
  text "Quantity" at 3131.16,3162.98 h72
  text "Finished Hole Size" at 3463.16,3162.98 h72
  text "Plated" at 4099.72,3162.98 h72
  text "Hole Type" at 4358.86,3162.98 h72
  text "Drill Layer Pair" at 4734.02,3162.98 h72
  text "Hole Tolerance" at 5458.35,3162.98 h72
  text "1" at 3131.16,3038.66 h60
  text "70.08mil (1.780mm)" at 3463.16,3038.66 h60
  text "NPTH" at 4099.72,3038.66 h60
  text "Round" at 4358.86,3038.66 h60
  text "Top Layer - Bottom Layer" at 4734.02,3038.66 h60
  text "14" at 3131.16,2914.34 h60
  text "7.87mil (0.200mm)" at 3463.16,2914.34 h60
  text "PTH" at 4099.72,2914.34 h60
  text "Round" at 4358.86,2914.34 h60
  text "Top Layer - Bottom Layer" at 4734.02,2914.34 h60
  text "125" at 3131.16,2790.02 h60
  text "12.00mil (0.305mm)" at 3463.16,2790.02 h60
  text "PTH" at 4099.72,2790.02 h60
  text "Round" at 4358.86,2790.02 h60
  text "Top Layer - Bottom Layer" at 4734.02,2790.02 h60
  text "28" at 3131.16,2665.7 h60
  text "28.00mil (0.711mm)" at 3463.16,2665.7 h60
  text "PTH" at 4099.72,2665.7 h60
  text "Round" at 4358.86,2665.7 h60
  text "Top Layer - Bottom Layer" at 4734.02,2665.7 h60
  text "20" at 3131.16,2541.38 h60
  text "40.00mil (1.016mm)" at 3463.16,2541.38 h60
  text "PTH" at 4099.72,2541.38 h60
  text "Round" at 4358.86,2541.38 h60
  text "Top Layer - Bottom Layer" at 4734.02,2541.38 h60
  text "49" at 3131.16,2417.06 h60
  text "40.16mil (1.020mm)" at 3463.16,2417.06 h60
  text "PTH" at 4099.72,2417.06 h60
  text "Round" at 4358.86,2417.06 h60
  text "Top Layer - Bottom Layer" at 4734.02,2417.06 h60
  text "12" at 3131.16,2292.74 h60
  text "55.00mil (1.397mm)" at 3463.16,2292.74 h60
  text "PTH" at 4099.72,2292.74 h60
  text "Round" at 4358.86,2292.74 h60
  text "Top Layer - Bottom Layer" at 4734.02,2292.74 h60
  text "249 Total" at 3131.16,2168.42 h60
  text ".Layer_Name" at 577,-858.49 h60
M17 Embedded Cavity:
  text ".Layer_Name" at 577,-858.49 h60
M18 Embedded Assembly:
  text ".Layer_Name" at 577,-858.49 h60
M19 Embedded Keepout:
  text ".Layer_Name" at 577,-858.49 h60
